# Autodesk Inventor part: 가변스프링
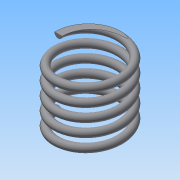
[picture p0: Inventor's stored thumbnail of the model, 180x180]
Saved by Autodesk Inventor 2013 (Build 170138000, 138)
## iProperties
Created: 2016-03
Part Number: 가변스프링
Material: Generic
Document SubType Name: Modeling
Designer: Administrator
Density: 1 g/cm^3
Mass: 0.818986 g
Surface Area: 16.6928 cm^2
Volume: 0.818986 cm^3
Author: Administrator
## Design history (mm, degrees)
sketch "스케치1"
  geometry: L1 (0, 0)-(8.5, 0); L2 (8.5, 20.5)-(0, 20.5); L3 (0, 20.5)-(0, 0); C1 r 1 at (8.5, 0)
  constraints: 6 end point, 2 parallel, 1 centre point, 1 coincident, 1 horizontal, 1 vertical
  dimensions: "d0" = 2 diameter of C1; "d1" = 17 diameter of C1.centre L3; "d2" = 20.5 distance between parallel lines of L1 L2 (derived)
feature "코일1" sketch "스케치1" pitch "d3" = 10; turns "d5" = 5; dims "d4" = 20.5 (= d2), "d6" = 0, angle "d7" = 90 deg, angle "d8" = 90 deg, "d9" = 0, "d10" = 0
sketch "스케치2"
  geometry: L1 (-10, 20.5)-(10, 20.5); L2 (10, 20.5)-(10, 0); L3 (10, 0)-(-10, 0); L4 (-10, 0)-(-10, 20.5); 2 further points
  constraints: 8 end point, 2 parallel, 1 coincident, 1 horizontal, 1 midpoint, 1 perpendicular
  dimensions: "d11" = 20.5 distance between parallel lines of L3 L1 (derived); "d13" = 20 distance of L1.start L1.end
extrude "돌출1" sketch "스케치2" stored distance "d14" = 10; taper "d15" = 0 deg
node "솔리드1"
